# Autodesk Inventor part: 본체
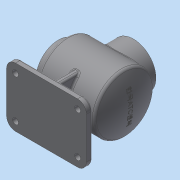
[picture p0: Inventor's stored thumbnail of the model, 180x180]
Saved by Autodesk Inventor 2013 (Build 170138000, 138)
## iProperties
Created: 2016-09
Part Number: 본체
Material: Generic
Document SubType Name: Modeling
Designer: Administrator
Density: 1 g/cm^3
Author: Administrator
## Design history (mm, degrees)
sketch "스케치1"
  geometry: L1 (-61, 0)-(61, 0); L2 (-61, 0)-(-61, 38); L3 (-61, 38)-(-49, 38); L4 (-49, 38)-(-49, 50); L5 (-49, 50)-(49.562, 50); A1 r 115 centre (-54, 0) between (61, 0) and (49.562, 50); 2 further points
  constraints: 10 end point, 2 parallel, 2 point on circle, 1 centre point, 1 coincident, 1 horizontal, 1 midpoint, 1 perpendicular, 1 point on line, 1 vertical
  dimensions: "d0" = 122 distance of L1.start L1.end; "d3" = 100 diameter of L5 L1; "d4" = 76 diameter of L3 L1; "d5" = 115 radius of A1; "d93" = 110 distance from line of L1.end L4
revolve "회전1" sketch "스케치1" stored, may be unused: angle "d6" = 90 deg
sketch "스케치2"
  geometry: L1 (61, 38)-(61, -38) reference; L2 (49, 50)-(-49.562, 50) reference; L3 (61, 0)-(-61, 0); L4 (61, 27)-(46, 27); L5 (46, 27)-(46, 47); L6 (46, 47)-(-47.661, 47); L7 (49, 50)-(49, -50) reference; L8 (61, 27)-(61, 0); A1 r 115 centre (54, 0) between (-49.562, 50) and (-49.562, -50) reference; A2 r 112 centre (54, 0) between (-47.661, 47) and (-58, 0); 1 further point
  constraints: 10 end point, 3 point on circle, 2 parallel, 2 perpendicular, 2 point on line, 1 centre point, 1 midpoint
  dimensions: "d8" = 3 radial gap between concentric circles of A1 A2; "d9" = 3 distance between parallel lines of L2 L6; "d10" = 3 distance between parallel lines of L7 L5; "d11" = 54 diameter of L4 L3
revolve "회전2" sketch "스케치2" stored, may be unused: angle "d12" = 90 deg
fillet "모깎기1" dims "d13" = 5
fillet "모깎기2" dims "d14" = 3
fillet "모깎기3" dims "d15" = 2
sketch "스케치3"
  geometry: C1 r 27 at (0, 0) reference; 1 further point
  constraints: 1 vertical alignment
  dimensions: "d16" = 32.5 distance of C1.centre point (0, 32.5)
hole "구멍1" sketch "스케치3" at (0, 32.5) diameter "d17" = 3.242; stored, may be unused: countersink angle "d21" = 90 deg, drill point angle "d23" = 118 deg; dims "d18" = 8, "d19" = 4, "d20" = 2, "d22" = 10
node "작업 평면1"
sketch "스케치4"
  geometry: L1 (49, 45)-(49, -45) reference; C1 r 38 at (-1, 0); 1 further point
  constraints: 1 centre point, 1 horizontal alignment
  dimensions: "d28" = 76 diameter of C1; "d30" = 50 distance from line of C1.centre L1
extrude "돌출1" join sketch "스케치4" stored distance "d31" = 10; taper "d32" = 0 deg
sketch "스케치5"
  geometry: C1 r 38 at (0, 0) reference; C2 r 27 at (0, 0); 1 further point
  constraints: 1 centre point, 1 coincident
  dimensions: "d33" = 54 diameter of C2
extrude "돌출2" cut sketch "스케치5" stored distance "d35" = 10; taper "d36" = 0 deg
sketch "스케치6"
  geometry: C1 r 27 at (0, 0) reference; 2 further points
  constraints: 1 vertical alignment
  dimensions: "d37" = 32.5 distance of C1.centre point (0, 32.5)
hole "구멍2" sketch "스케치6" at (0, 32.5) diameter "d38" = 3.242; stored, may be unused: countersink angle "d42" = 90 deg, drill point angle "d44" = 118 deg; dims "d39" = 8, "d40" = 4, "d41" = 2, "d43" = 10
fillet "모깎기4" dims "d48" = 3
node "작업 평면2"
sketch "스케치7"
  geometry: L1 (-66.5, 50)-(68.5, 50); L2 (68.5, 50)-(68.5, -50); L3 (68.5, -50)-(-66.5, -50); L4 (-66.5, -50)-(-66.5, 50); C1 r 38 at (1, 0) reference; 3 further points
  constraints: 8 end point, 2 midpoint, 2 parallel, 1 horizontal, 1 horizontal alignment, 1 perpendicular, 1 vertical alignment
  dimensions: "d50" = 135 distance of L1.start L1.end; "d52" = 100 distance of L1.end L2.end
extrude "돌출3" join sketch "스케치7" distance "d53" = 10; taper "d54" = 0 deg
fillet "모깎기7" dims "d81" = 15
fillet "모깎기8" dims "d82" = 3
sketch "스케치11"
  geometry: C1 r 5 at (-51.5, 35); C2 r 5 at (53.5, 35); C3 r 5 at (53.5, -35); C4 r 5 at (-51.5, -35); A1 r 15 centre (53.5, -35) between (53.5, -50) and (68.5, -35) reference; A2 r 15 centre (53.5, 35) between (68.5, 35) and (53.5, 50) reference; A3 r 15 centre (-51.5, 35) between (-51.5, 50) and (-66.5, 35) reference; A4 r 15 centre (-51.5, -35) between (-66.5, -35) and (-51.5, -50) reference; 1 further point
  constraints: 4 centre point, 4 coincident, 3 equal radius
  dimensions: "d83" = 10 diameter of C1
extrude "돌출5" cut sketch "스케치11" distance "d85" = 10; taper "d86" = 0 deg
node "작업 평면3"
sketch "스케치12"
  geometry: 2 further points
  constraints: 1 coincident, 1 other
feature "엠보싱1" sketch "스케치12" dims "d0" = 122, "d88" = 0.5, "d89" = 0
chamfer "모따기1" distance "d90" = 1; stored, may be unused: second distance "d91" = 2, angle "d92" = 45 deg
node "작업 평면4"
sketch "스케치13"
  geometry: L1 (0, 10)-(70, 10) reference; L2 (-5, 10)-(5, 10) reference; L3 (70, 10)-(82, 10) reference; L4 (-12, 10)-(0, 10) reference; L5 (-5, 52)-(-5, 10); L6 (75, 52)-(75, 10); A1 r 50 centre (35, 82) between (-5, 52) and (75, 52) reference; 1 further point
  constraints: 4 end point, 2 perpendicular, 2 point on circle, 2 point on line
  dimensions: "d95" = 40 distance from line of L5 point (35, 82); "d96" = 40 distance from line of L6 point (35, 82)
extrude "돌출6" join sketch "스케치13" stored distance "d97" = 10; taper "d98" = 0 deg
sketch "스케치14"
  geometry: L1 (-44, -50)-(46.374, -50) reference; L2 (-4, -30)-(-4, -72) reference; L3 (-51.5, -72)-(53.5, -72) reference; L4 (29, 65)-(-27, 65) reference; L5 (1, 65)-(1, -8.254); L6 (-37.075, -50)-(-39, -72); 1 further point
  constraints: 4 end point, 2 point on line, 1 midpoint, 1 perpendicular
  dimensions: "d100" = 95 deg angle of L6 L3; "d120" = 40 distance from line of L5 L6.end
feature "리브3" sketch "스케치14" dims "d101" = 1, "d102" = 10, "d103" = 0, "d104" = 0, "d105" = 1, "d106" = 1
sketch "스케치15"
  geometry: L1 (-51.5, -72)-(53.5, -72) reference; L2 (-44, -50)-(46.374, -50) reference; L3 (29, 65)-(-27, 65) reference; L4 (1, 65)-(1, -19.091); L5 (39.075, -50)-(41, -72); 1 further point
  constraints: 4 end point, 2 point on line, 1 midpoint, 1 perpendicular
  dimensions: "d107" = 40 distance from line of L4 L5.end; "d109" = 95 deg angle of L5 L1
feature "리브4" sketch "스케치15" dims "d111" = 1, "d112" = 10, "d113" = 0, "d114" = 0, "d115" = 1, "d116" = 1
fillet "모깎기9" dims "d117" = 3
fillet "모깎기10" dims "d118" = 3
fillet "모깎기11" dims "d119" = 3
node "솔리드1"
pattern_circular "원형 패턴1" dims angle "d25" = 360 deg
pattern_circular "원형 패턴2" dims angle "d46" = 360 deg
other parameters: "d27" = 65, "d49" = -82, "d87" = 123.75, "d94" = -67.5
